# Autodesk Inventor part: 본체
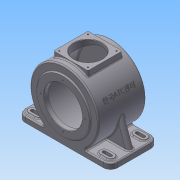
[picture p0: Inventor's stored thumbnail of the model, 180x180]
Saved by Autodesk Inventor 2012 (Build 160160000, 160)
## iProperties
Created: 2015-06
Part Number: 본체
Material: 알루미늄-6061
Document SubType Name: Modeling
Designer: User
Density: 2.71 g/cm^3
Mass: 3276.66 g
Surface Area: 2300.55 cm^2
Volume: 1209.1 cm^3
Author: User
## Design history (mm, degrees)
sketch "스케치1"
  geometry: C1 r 85 at (0, 0); 1 further point
  constraints: 1 centre point, 1 coincident
  dimensions: "d0" = 170 diameter of C1
extrude "돌출1" new body sketch "스케치1" stored distance "d1" = 118; taper "d2" = 0 deg
node "작업 평면1"
sketch "스케치2"
  geometry: L1 (-97, 59)-(97, 59); L2 (115, 41)-(115, -41); L3 (97, -59)-(-97, -59); L4 (-115, -41)-(-115, 41); A1 r 18 centre (-97, 41) between (-97, 59) and (-115, 41); A2 r 18 centre (-97, -41) between (-115, -41) and (-97, -59); A3 r 18 centre (97, -41) between (97, -59) and (115, -41); A4 r 18 centre (97, 41) between (115, 41) and (97, 59); 6 further points
  constraints: 8 end point, 8 point on circle, 8 tangent, 6 point on line, 4 centre point, 3 equal radius, 2 midpoint, 2 parallel, 1 horizontal, 1 horizontal alignment, 1 perpendicular, 1 vertical alignment
  dimensions: "d4" = 118 distance of point (-115, -59) point (-115, 59); "d5" = 230 distance of point (-115, 59) point (115, 59); "d6" = 18 radius of A1
extrude "돌출2" join sketch "스케치2" distance "d7" = 14; taper "d8" = 0 deg
sketch "스케치3"
  geometry: L1 (-42.5, 42.5)-(42.5, 42.5); L2 (42.5, 42.5)-(42.5, -42.5); L3 (42.5, -42.5)-(-42.5, -42.5); L4 (-42.5, -42.5)-(-42.5, 42.5); 3 further points
  constraints: 8 end point, 2 midpoint, 2 parallel, 2 perpendicular, 1 horizontal, 1 horizontal alignment, 1 vertical alignment
  dimensions: "d9" = 85 distance of L1.start L1.end
extrude "돌출3" join sketch "스케치3" distance "d10" = 88; taper "d11" = 0 deg
sketch "스케치4"
  geometry: C1 r 65 at (0, 0); A1 r 85 centre (0, 0) between (46.733, -71) and (-46.733, -71) reference
  constraints: 1 centre point, 1 coincident
  dimensions: "d12" = 130 diameter of C1
extrude "돌출4" join sketch "스케치4" distance "d13" = 3; taper "d14" = 0 deg
sketch "스케치5"
  geometry: C1 r 65 at (0, 0); A1 r 85 centre (0, 0) between (46.733, -71) and (-46.733, -71) reference
  constraints: 1 centre point, 1 coincident
  dimensions: "d15" = 130 diameter of C1
extrude "돌출5" join sketch "스케치5" distance "d16" = 13; taper "d17" = 0 deg
sketch "스케치6"
  geometry: L1 (-46.733, -59)-(-97, -59) reference; L2 (-97, 50)-(-81, 50); L3 (-81, 32)-(-97, 32); L4 (-97, -32)-(-81, -32); L5 (-81, -50)-(-97, -50); L6 (81, 50)-(97, 50); L7 (97, 32)-(81, 32); L8 (81, -32)-(97, -32); L9 (97, -50)-(81, -50); L10 (115, -41)-(115, 41) reference; L11 (-81, 45)-(-97, 45); L12 (-97, 37)-(-81, 37); L13 (97, 45)-(81, 45); L14 (81, 37)-(97, 37); L15 (97, -37)-(81, -37); L16 (81, -45)-(97, -45); L17 (-81, -37)-(-97, -37); L18 (-97, -45)-(-81, -45); A1 r 18 centre (-97, 41) between (-97, 59) and (-115, 41) reference; A2 r 18 centre (-97, -41) between (-115, -41) and (-97, -59) reference; A3 r 9 centre (-81, 41) between (-81, 32) and (-81, 50); A4 r 9 centre (-97, 41) between (-97, 50) and (-97, 32); A5 r 9 centre (-81, -41) between (-81, -50) and (-81, -32); A6 r 9 centre (-97, -41) between (-97, -32) and (-97, -50); A7 r 9 centre (97, 41) between (97, 32) and (97, 50); A8 r 9 centre (81, 41) between (81, 50) and (81, 32); A9 r 9 centre (97, -41) between (97, -50) and (97, -32); A10 r 9 centre (81, -41) between (81, -32) and (81, -50); A11 r 4 centre (-97, 41) between (-97, 45) and (-97, 37); A12 r 4 centre (-81, 41) between (-81, 37) and (-81, 45); A13 r 4 centre (81, 41) between (81, 45) and (81, 37); A14 r 4 centre (97, 41) between (97, 37) and (97, 45); A15 r 4 centre (81, -41) between (81, -37) and (81, -45); A16 r 4 centre (97, -41) between (97, -45) and (97, -37); A17 r 4 centre (-97, -41) between (-97, -37) and (-97, -45); A18 r 4 centre (-81, -41) between (-81, -45) and (-81, -37); 1 further point
  constraints: 32 end point, 32 point on circle, 16 centre point, 16 tangent, 12 parallel, 6 equal radius, 4 coincident, 2 equal length, 2 horizontal alignment, 2 vertical alignment, 12 other
  dimensions: "d18" = 16 distance of A3.centre A1.centre; "d19" = 18 distance between parallel lines of L3 L2; "d20" = 18 distance from line of A7.centre L10; "d21" = 8 distance between parallel lines of L12 L11
extrude "돌출6" join sketch "스케치6" distance "d22" = 3; taper "d23" = 0 deg
extrude "돌출7" cut sketch "스케치6" stored distance "d24" = 30; taper "d25" = 0 deg
sketch "스케치7"
  geometry: L1 (-115, -71)-(-97, -71) reference; L2 (-109, -71)-(-84.87, -4.703); L3 (97, -71)-(115, -71) reference; L4 (109, -71)-(84.87, -4.703); L5 (-84.87, -4.703)-(84.87, -4.703); L6 (-109, -71)-(109, -71); A1 r 85 centre (0, 0) between (46.733, -71) and (-46.733, -71) reference; 1 further point
  constraints: 8 end point, 2 point on circle, 2 point on line
  dimensions: "d26" = 6 distance of L2.start L1.start; "d27" = 110 deg angle of L2 L1; "d28" = 6 distance of L3.end L4.start; "d29" = 110 deg angle of L3 L4
extrude "돌출8" join sketch "스케치7" stored distance "d30" = 15; taper "d31" = 0 deg
node "작업 평면2"
  node "작업축2"
sketch "스케치11"
  geometry: L1 (40.533, -6.549)-(-40.533, -6.549); L2 (-40.533, -6.549)-(-40.533, 6.549); L3 (-40.533, 6.549)-(40.533, 6.549); L4 (40.533, 6.549)-(40.533, -6.549); 4 further points
  constraints: 2 horizontal alignment, 2 midpoint, 1 coincident, 1 vertical alignment, 2 other
feature "엠보싱1" sketch "스케치11" dims "d0" = 170, "d61" = 0.5, "d62" = 0
sketch "스케치8"
  geometry: L1 (-85, 82.6)-(-85, -82.6) reference; L2 (88, 42.5)-(88, -42.5) reference; L3 (-65, 59)-(65, 59) reference; L4 (65, -59)-(-65, -59) reference; L5 (0, 51)-(77, 51); L6 (77, 51)-(77, -51); L7 (77, -51)-(0, -51); L8 (0, 51)-(0, -51); 1 further point
  constraints: 10 end point, 3 parallel, 1 vertical, 1 vertical alignment
  dimensions: "d32" = 8 distance between parallel lines of L4 L7; "d33" = 8 distance between parallel lines of L5 L3; "d34" = 11 distance between parallel lines of L2 L6
revolve "회전1" sketch "스케치8" stored, may be unused: angle "d35" = 90 deg
hole "구멍1" diameter "d38" = 95; stored, may be unused: countersink angle "d42" = 90 deg, drill point angle "d44" = 118 deg; dims "d36" = 10, "d37" = 10, "d39" = 6, "d40" = 4, "d41" = 2, "d43" = 50
sketch "스케치9"
  geometry: C1 r 35 at (0, 0); 1 further point
  constraints: 1 centre point, 1 coincident
  dimensions: "d45" = 70 diameter of C1
extrude "돌출9" cut sketch "스케치9" distance "d46" = 30; taper "d47" = 0 deg
sketch "스케치10"
  geometry: C1 r 77 at (0, 0) reference; C2 r 31 at (0, 0)
  constraints: 1 centre point, 1 coincident
  dimensions: "d48" = 62 diameter of C2
extrude "돌출10" join sketch "스케치10" distance "d49" = 3.5; taper "d50" = -25 deg
hole "구멍2" diameter "d53" = 30; stored, may be unused: countersink angle "d57" = 90 deg, drill point angle "d59" = 0 deg; dims "d51" = 10, "d52" = 10, "d54" = 6, "d55" = 47, "d56" = 14, "d58" = 17
sketch "스케치12"
  geometry: L1 (-35.5, 35.5)-(35.5, 35.5); L2 (35.5, 35.5)-(35.5, -35.5); L3 (35.5, -35.5)-(-35.5, -35.5); L4 (-35.5, -35.5)-(-35.5, 35.5); C1 r 35 at (0, 0) reference; 6 further points
  constraints: 8 end point, 4 coincident, 2 midpoint, 2 parallel, 2 perpendicular, 1 horizontal, 1 horizontal alignment, 1 vertical alignment
  dimensions: "d63" = 71 distance of L1.start L1.end
hole "구멍3" sketch "스케치12" at (-35.5, 35.5), (35.5, 35.5), (35.5, -35.5), (-35.5, -35.5) diameter "d64" = 3.242; stored, may be unused: countersink angle "d68" = 90 deg, drill point angle "d70" = 0 deg; dims "d65" = 10, "d66" = 47, "d67" = 14, "d69" = 13
chamfer "모따기1" distance "d71" = 1; stored, may be unused: second distance "d72" = 2, angle "d73" = 45 deg
chamfer "모따기2" distance "d74" = 1; stored, may be unused: second distance "d75" = 2, angle "d76" = 45 deg
chamfer "모따기3" distance "d77" = 1; stored, may be unused: second distance "d78" = 2, angle "d79" = 45 deg
fillet "모깎기1" dims "d80" = 3
fillet "모깎기2" dims "d81" = 3
fillet "모깎기3" dims "d82" = 3
fillet "모깎기4" dims "d83" = 3
fillet "모깎기5" dims "d84" = 3
fillet "모깎기6" dims "d85" = 7.5
sketch "스케치13"
  geometry: C1 r 65 at (0, 0) reference; 1 further point
  constraints: 1 vertical alignment
  dimensions: "d86" = 55 distance of point (0, 55) C1.centre
hole "구멍4" sketch "스케치13" at (0, 55) diameter "d87" = 3.242; stored, may be unused: countersink angle "d91" = 90 deg, drill point angle "d93" = 118 deg; dims "d88" = 30, "d89" = 4, "d90" = 2, "d92" = 50
fillet "모깎기7" dims "d97" = 0.3
fillet "모깎기8" dims "d98" = 7.5
fillet "모깎기9" dims "d99" = 3
fillet "모깎기10" dims "d100" = 3
fillet "모깎기11" dims "d101" = 3
fillet "모깎기12" dims "d102" = 3
fillet "모깎기13" dims "d103" = 3
node "솔리드1"
pattern_circular "원형 패턴1" dims angle "d95" = 360 deg
other parameters: "d3" = -85, "d60" = -65 deg
